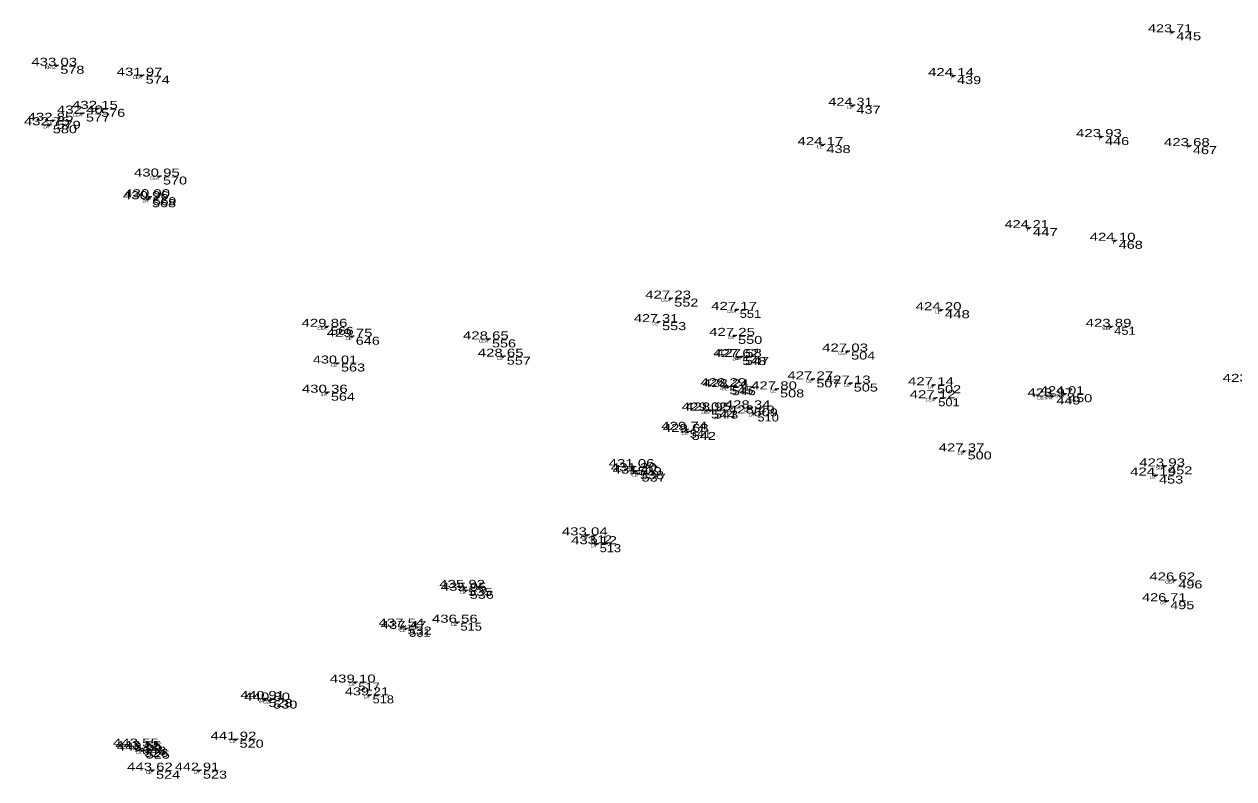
# Model space of a CAD drawing. Extents: x -639373 to -639056, y -1138651 to -1138359.
# Drawn here: x -639295.3 to -639181.9, y -1138643.1 to -1138572.3 of the extents above; entities that cross this region are included whole.
import ezdxf
from ezdxf.enums import TextEntityAlignment as Align

# ---------------------------------------------------------------- set-up
doc = ezdxf.new("R2010")
doc.units = 0
doc.header["$LTSCALE"] = 0.3
doc.header["$PDMODE"] = 32
doc.header["$PDSIZE"] = 0.15
for name, color, linetype in [('11', 7, 'Continuous'), ('12', 7, 'Continuous'), ('13', 7, 'Continuous'), ('14', 7, 'Continuous'), ('57', 7, 'Continuous')]:
    doc.layers.add(name, color=color, linetype=linetype)

msp = doc.modelspace()

# ---------------------------------------------------------------- linework, layer by layer
at = {"layer": '11'}
for p in [(-639187.67, -1138573.11), (-639292.26, -1138576.25), (-639284.26, -1138577.18), (-639208.2, -1138577.22), (-639217.63, -1138580), (-639289.86, -1138580.73), (-639288.44, -1138580.29), (-639292.96, -1138581.83), (-639292.61, -1138581.41), (-639194.33, -1138582.94), (-639220.44, -1138583.69), (-639186.09, -1138583.79), (-639282.64, -1138586.64), (-639283.67, -1138588.77), (-639283.55, -1138588.58), (-639201.11, -1138591.48), (-639193.05, -1138592.67), (-639234.71, -1138598.09), (-639228.53, -1138599.15), (-639209.36, -1138599.18), (-639235.85, -1138600.3), (-639266.93, -1138600.74), (-639228.72, -1138601.59), (-639193.43, -1138600.74), (-639264.57, -1138601.67), (-639251.8, -1138601.92), (-639250.41, -1138603.54), (-639228.34, -1138603.58), (-639228.08, -1138603.56), (-639218.13, -1138603.06), (-639265.95, -1138604.18), (-639221.39, -1138605.67), (-639217.88, -1138606.06), (-639266.9, -1138606.92), (-639229.54, -1138606.31), (-639229.32, -1138606.4), (-639224.79, -1138606.61), (-639210.08, -1138606.22), (-639198.89, -1138607.27), (-639197.79, -1138607.06), (-639227.26, -1138608.39), (-639209.92, -1138607.44), (-639231.29, -1138608.59), (-639230.97, -1138608.59), (-639226.87, -1138608.87), (-639233.21, -1138610.4), (-639233.07, -1138610.6), (-639207.21, -1138612.43), (-639238.14, -1138613.9), (-639188.41, -1138613.83), (-639237.93, -1138614.28), (-639237.77, -1138614.51), (-639189.26, -1138614.69), (-639242.53, -1138620.3), (-639241.66, -1138621.13), (-639254.02, -1138625.23), (-639187.46, -1138624.53), (-639253.88, -1138625.5), (-639188.22, -1138626.48), (-639254.71, -1138628.49), (-639259.71, -1138628.86), (-639259.52, -1138629.07), (-639264.28, -1138634.11), (-639272.75, -1138635.65), (-639262.95, -1138635.31), (-639272.3, -1138635.8), (-639284.6, -1138640.12), (-639275.46, -1138639.47), (-639284.38, -1138640.33), (-639284.25, -1138640.49), (-639283.29, -1138642.38), (-639278.89, -1138642.37)]:
    msp.add_point(p, dxfattribs=at)

# ---------------------------------------------------------------- texts
at = {"layer": '12'}
for s, width, p in [('433.03 ', 1.4, (-639292.26, -1138576.25)), ('431.97 ', 1.4, (-639284.26, -1138577.18)), ('432.40 ', 1.4, (-639289.86, -1138580.73)), ('432.15 ', 1.4, (-639288.44, -1138580.29)), ('432.75 ', 1.4, (-639292.96, -1138581.83)), ('432.85 ', 1.4, (-639292.61, -1138581.41)), ('430.95 ', 1.4, (-639282.64, -1138586.64)), ('430.90 ', 1.4, (-639283.55, -1138588.58)), ('430.96 ', 1.4, (-639283.669, -1138588.77)), ('427.23 ', 1.4, (-639234.71, -1138598.09)), ('427.17 ', 1.4, (-639228.53, -1138599.15)), ('429.86 ', 1.4, (-639266.929, -1138600.74)), ('427.31 ', 1.35, (-639235.849, -1138600.3)), ('429.75 ', 1.4, (-639264.57, -1138601.67)), ('428.65 ', 1.4, (-639251.8, -1138601.92)), ('427.25 ', 1.4, (-639228.72, -1138601.59)), ('427.03 ', 1.4, (-639218.13, -1138603.06)), ('430.01 ', 1.35, (-639265.949, -1138604.18)), ('428.65 ', 1.4, (-639250.41, -1138603.54)), ('427.62 ', 1.4, (-639228.34, -1138603.58)), ('427.58 ', 1.4, (-639228.08, -1138603.56)), ('427.27 ', 1.4, (-639221.39, -1138605.67)), ('428.29 ', 1.4, (-639229.54, -1138606.31)), ('428.24 ', 1.4, (-639229.32, -1138606.4)), ('427.80 ', 1.4, (-639224.79, -1138606.61)), ('427.13 ', 1.4, (-639217.88, -1138606.06)), ('427.14 ', 1.4, (-639210.08, -1138606.22)), ('430.36 ', 1.4, (-639266.899, -1138606.92)), ('427.12 ', 1.4, (-639209.92, -1138607.44)), ('423.97 ', 1.4, (-639198.89, -1138607.27)), ('424.01 ', 1.35, (-639197.789, -1138607.06)), ('429.02 ', 1.4, (-639231.29, -1138608.59)), ('428.95 ', 1.4, (-639230.97, -1138608.59)), ('428.34 ', 1.4, (-639227.26, -1138608.39)), ('428.49 ', 1.4, (-639226.87, -1138608.87)), ('429.74 ', 1.4, (-639233.21, -1138610.4)), ('429.68 ', 1.4, (-639233.07, -1138610.6)), ('427.37 ', 1.4, (-639207.21, -1138612.43)), ('431.06 ', 1.4, (-639238.139, -1138613.9)), ('431.20 ', 1.4, (-639237.93, -1138614.28)), ('431.17 ', 1.4, (-639237.77, -1138614.51)), ('424.19 ', 1.4, (-639189.26, -1138614.69)), ('423.93 ', 1.4, (-639188.41, -1138613.83)), ('433.04 ', 1.4, (-639242.53, -1138620.3)), ('433.12 ', 1.4, (-639241.66, -1138621.13)), ('426.62 ', 1.4, (-639187.46, -1138624.53)), ('435.92 ', 1.4, (-639254.02, -1138625.23)), ('435.95 ', 1.4, (-639253.88, -1138625.5)), ('426.71 ', 1.35, (-639188.219, -1138626.48)), ('437.54 ', 1.4, (-639259.71, -1138628.86)), ('437.47 ', 1.4, (-639259.52, -1138629.07)), ('436.56 ', 1.4, (-639254.709, -1138628.49)), ('439.10 ', 1.4, (-639264.28, -1138634.11)), ('440.91 ', 1.35, (-639272.749, -1138635.65)), ('440.80 ', 1.4, (-639272.3, -1138635.8)), ('439.21 ', 1.35, (-639262.949, -1138635.31)), ('441.92 ', 1.4, (-639275.46, -1138639.47)), ('443.55 ', 1.4, (-639284.6, -1138640.12)), ('443.55 ', 1.4, (-639284.38, -1138640.33)), ('443.55 ', 1.4, (-639284.25, -1138640.49)), ('443.62 ', 1.4, (-639283.29, -1138642.38)), ('442.91 ', 1.35, (-639278.889, -1138642.37))]:
    msp.add_text(s, height=0.75, dxfattribs=dict(at, width=width)).set_placement(p, align=Align.CENTER)
at = {"layer": '13'}
for s, width, p in [(' 445', 1.4, (-639187.67, -1138573.86)), (' 578', 1.35, (-639292.26, -1138577)), (' 574', 1.35, (-639284.26, -1138577.93)), (' 439', 1.35, (-639208.2, -1138577.97)), (' 437', 1.35, (-639217.63, -1138580.75)), (' 577', 1.35, (-639289.86, -1138581.48)), (' 576', 1.35, (-639288.44, -1138581.04)), (' 580', 1.35, (-639292.96, -1138582.58)), (' 579', 1.35, (-639292.61, -1138582.16)), (' 446', 1.35, (-639194.33, -1138583.69)), (' 438', 1.35, (-639220.44, -1138584.44)), (' 467', 1.35, (-639186.09, -1138584.54)), (' 570', 1.35, (-639282.64, -1138587.39)), (' 568', 1.35, (-639283.67, -1138589.52)), (' 569', 1.3, (-639283.55, -1138589.33)), (' 447', 1.4, (-639201.11, -1138592.23)), (' 468', 1.35, (-639193.05, -1138593.42)), (' 552', 1.35, (-639234.71, -1138598.84)), (' 551', 1.2, (-639228.53, -1138599.9)), (' 448', 1.4, (-639209.36, -1138599.93)), (' 553', 1.35, (-639235.85, -1138601.05)), (' 566', 1.3, (-639266.93, -1138601.49)), (' 451', 1.2, (-639193.43, -1138601.49)), (' 646', 1.35, (-639264.57, -1138602.42)), (' 556', 1.35, (-639251.8, -1138602.67)), (' 550', 1.35, (-639228.72, -1138602.34)), (' 557', 1.35, (-639250.41, -1138604.29)), (' 548', 1.35, (-639228.34, -1138604.33)), (' 547', 1.35, (-639228.08, -1138604.31)), (' 504', 1.35, (-639218.13, -1138603.81)), (' 563', 1.35, (-639265.95, -1138604.93)), (' 507', 1.35, (-639221.39, -1138606.42)), (' 505', 1.35, (-639217.88, -1138606.81)), (' 564', 1.35, (-639266.9, -1138607.67)), (' 545', 1.35, (-639229.54, -1138607.06)), (' 546', 1.35, (-639229.32, -1138607.15)), (' 508', 1.35, (-639224.79, -1138607.36)), (' 502', 1.35, (-639210.08, -1138606.97)), (' 450', 1.35, (-639197.79, -1138607.81)), (' 501', 1.2, (-639209.92, -1138608.19)), (' 449', 1.35, (-639198.89, -1138608.02)), (' 544', 1.4, (-639231.29, -1138609.34)), (' 543', 1.35, (-639230.97, -1138609.34)), (' 509', 1.35, (-639227.26, -1138609.14)), (' 510', 1.2, (-639226.87, -1138609.62)), (' 541', 1.2, (-639233.21, -1138611.15)), (' 542', 1.35, (-639233.07, -1138611.35)), (' 500', 1.35, (-639207.21, -1138613.18)), (' 539', 1.35, (-639238.14, -1138614.65)), (' 452', 1.35, (-639188.41, -1138614.58)), (' 538', 1.35, (-639237.93, -1138615.03)), (' 537', 1.35, (-639237.77, -1138615.26)), (' 453', 1.35, (-639189.26, -1138615.44)), (' 512', 1.2, (-639242.53, -1138621.05)), (' 513', 1.2, (-639241.66, -1138621.88)), (' 535', 1.35, (-639254.02, -1138625.98)), (' 496', 1.35, (-639187.46, -1138625.28)), (' 536', 1.35, (-639253.88, -1138626.25)), (' 495', 1.35, (-639188.22, -1138627.23)), (' 515', 1.2, (-639254.71, -1138629.24)), (' 532', 1.35, (-639259.71, -1138629.61)), (' 531', 1.2, (-639259.52, -1138629.82)), (' 517', 1.2, (-639264.28, -1138634.86)), (' 518', 1.2, (-639262.95, -1138636.06)), (' 528', 1.35, (-639272.75, -1138636.4)), (' 530', 1.35, (-639272.3, -1138636.55)), (' 648', 1.35, (-639284.6, -1138640.87)), (' 520', 1.35, (-639275.46, -1138640.22)), (' 526', 1.35, (-639284.38, -1138641.08)), (' 525', 1.35, (-639284.25, -1138641.24)), (' 524', 1.35, (-639283.29, -1138643.13)), (' 523', 1.35, (-639278.89, -1138643.12))]:
    msp.add_text(s, height=0.75, dxfattribs=dict(at, width=width)).set_placement(p)
at = {"layer": '14'}
for s, width, p in [('423.71 ', 1.35, (-639187.669, -1138573.11)), ('424.14 ', 1.4, (-639208.2, -1138577.22)), ('424.31 ', 1.35, (-639217.629, -1138580)), ('423.93 ', 1.4, (-639194.33, -1138582.94)), ('424.17 ', 1.4, (-639220.44, -1138583.69)), ('423.68 ', 1.4, (-639186.09, -1138583.79)), ('424.21 ', 1.35, (-639201.109, -1138591.48)), ('424.10 ', 1.4, (-639193.05, -1138592.67)), ('424.20 ', 1.4, (-639209.36, -1138599.18)), ('423.89 ', 1.4, (-639193.43, -1138600.74)), ('423.68 ', 1.4, (-639180.58, -1138605.9))]:
    msp.add_text(s, height=0.75, dxfattribs=dict(at, width=width)).set_placement(p, align=Align.CENTER)
at = {"layer": '57'}
for s, width, p in [('T', 0.85, (-639187.67, -1138573.41)), ('KRIZ', 1.2, (-639292.259, -1138576.55)), ('T', 0.85, (-639208.2, -1138577.52)), ('CE', 0.9, (-639292.61, -1138581.71)), ('T', 0.85, (-639194.33, -1138583.24)), ('T', 0.85, (-639186.09, -1138584.09)), ('CE', 0.9, (-639283.55, -1138588.88)), ('T', 0.85, (-639201.11, -1138591.78)), ('T', 0.85, (-639193.05, -1138592.97)), ('CE', 0.9, (-639235.85, -1138600.6)), ('SIB', 1.25, (-639193.429, -1138601.04)), ('CE', 0.9, (-639264.57, -1138601.97)), ('CE', 0.9, (-639228.72, -1138601.89)), ('CE', 0.9, (-639250.41, -1138603.84)), ('CE', 0.9, (-639228.08, -1138603.86)), ('CE', 0.9, (-639265.95, -1138604.48)), ('CE', 0.9, (-639221.39, -1138605.97)), ('CE', 0.9, (-639217.88, -1138606.36)), ('CE', 0.9, (-639229.32, -1138606.7)), ('CE', 0.9, (-639224.79, -1138606.91)), ('PA SIA SIB', 1.4, (-639197.789, -1138607.36)), ('LE PA', 1.25, (-639198.89, -1138607.57)), ('CE', 0.9, (-639230.97, -1138608.89)), ('CE', 0.9, (-639227.26, -1138608.69)), ('CE', 0.9, (-639233.07, -1138610.9)), ('CE', 0.9, (-639207.21, -1138612.73)), ('HR', 0.85, (-639238.139, -1138614.2)), ('SIA', 1.25, (-639188.41, -1138614.13)), ('CE', 0.9, (-639237.77, -1138614.81)), ('CE', 0.9, (-639242.53, -1138620.6)), ('CE', 0.9, (-639253.88, -1138625.8)), ('CE', 0.9, (-639188.22, -1138626.78)), ('CE', 0.9, (-639254.71, -1138628.79)), ('CE', 0.9, (-639259.52, -1138629.37)), ('CE', 0.9, (-639264.28, -1138634.41)), ('CE', 0.9, (-639272.3, -1138636.1)), ('CE', 0.9, (-639275.46, -1138639.77)), ('CE', 0.9, (-639284.25, -1138640.79)), ('CE', 0.9, (-639283.29, -1138642.68))]:
    msp.add_text(s, height=0.3, dxfattribs=dict(at, width=width)).set_placement(p, align=Align.RIGHT)
for s, p in [('CEA', (-639284.26, -1138577.48)), ('LE', (-639217.63, -1138580.3)), ('CEA', (-639289.86, -1138581.03)), ('CEA', (-639288.44, -1138580.59)), ('ZA', (-639292.96, -1138582.13)), ('LE', (-639220.44, -1138583.99)), ('CEA', (-639282.64, -1138586.94)), ('ZA', (-639283.67, -1138589.07)), ('CEA', (-639234.71, -1138598.39)), ('CEA', (-639228.53, -1138599.45)), ('LE', (-639209.36, -1138599.48)), ('CEA', (-639266.93, -1138601.04)), ('CEA', (-639251.8, -1138602.22)), ('ZA', (-639228.34, -1138603.88)), ('CEA', (-639218.13, -1138603.36)), ('LA', (-639266.9, -1138607.22)), ('ZA', (-639229.54, -1138606.61)), ('LA', (-639210.08, -1138606.52)), ('CEA', (-639209.92, -1138607.74)), ('ZA', (-639231.29, -1138608.89)), ('LA', (-639226.87, -1138609.17)), ('ZA', (-639233.21, -1138610.7)), ('ZA', (-639237.93, -1138614.58)), ('LE', (-639189.26, -1138614.99)), ('LA', (-639241.66, -1138621.43)), ('ZA', (-639254.02, -1138625.53)), ('CEA', (-639187.46, -1138624.83)), ('ZA', (-639259.71, -1138629.16)), ('LA', (-639262.95, -1138635.61)), ('ZA', (-639272.75, -1138635.95)), ('LE', (-639284.6, -1138640.42)), ('ZA', (-639284.38, -1138640.63)), ('LA', (-639278.89, -1138642.67))]:
    msp.add_text(s, height=0.3, dxfattribs=at).set_placement(p, align=Align.RIGHT)

doc.saveas('drawing.dxf')
